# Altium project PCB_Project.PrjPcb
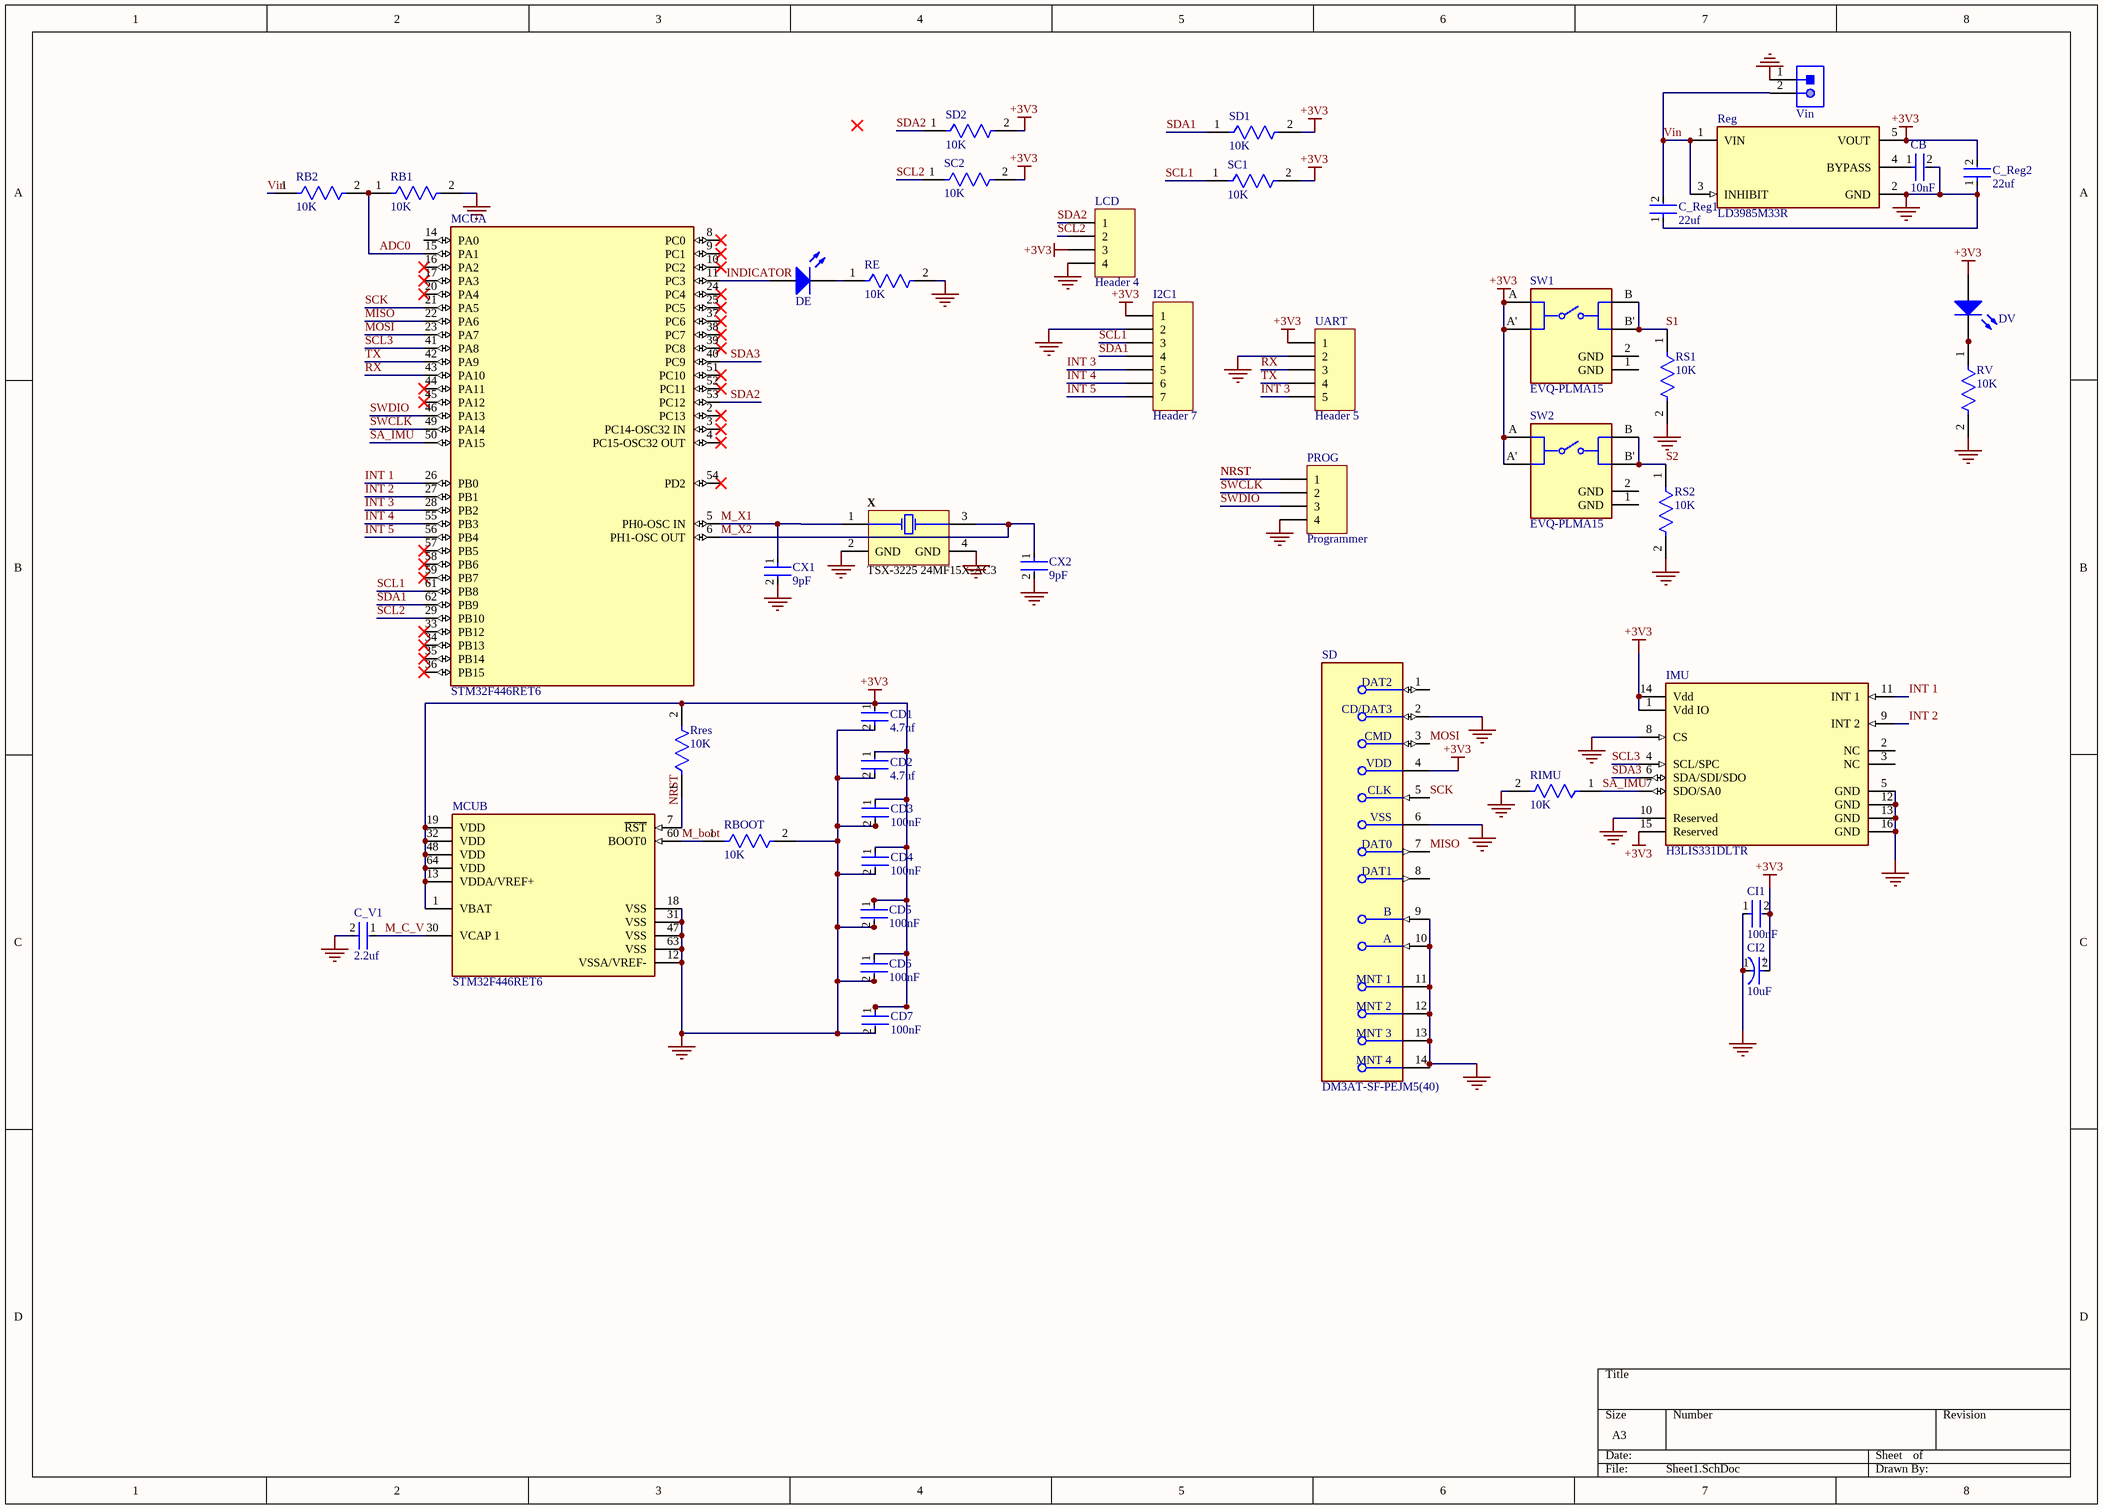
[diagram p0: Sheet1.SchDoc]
1 sheet, 42 parts. Net scope: global (net labels, ports and power ports of the same name join across sheets).
Board file: PCB1.PcbDoc

## Sheet Sheet1.SchDoc
size A3; SheetNumber: 1; SheetTotal: 1; SPICEModelCacheCNQVOYKR: <root> / <DocumentId>CNQVOYKR</DocumentId> / </root>

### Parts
C_Reg1  22uf  [FP-C2012-125-0_2-IPC_A]
C_Reg2  22uf  [FP-C2012-125-0_2-IPC_A]
C_V1  2.2uf  [FP-C1608-080-0_1-IPC_C]
CB  10nF  [FP-CC0603-DA-MFG]
CD1  4.7uf  [FP-C1608-080-0_1-IPC_C]
CD2  4.7uf  [FP-C1608-080-0_1-IPC_C]
CD3  100nF  [FP-CGA3E-0_3-0_1-IPC_A]
CD4  100nF  [FP-CGA3E-0_3-0_1-IPC_A]
CD5  100nF  [FP-CGA3E-0_3-0_1-IPC_A]
CD6  100nF  [FP-CGA3E-0_3-0_1-IPC_A]
CD7  100nF  [FP-CGA3E-0_3-0_1-IPC_A]
CI1  100nF  [FP-CGA3E-0_3-0_1-IPC_A]
CI2  10uF  [FP-SC-MFG]
CX1  9pF  [FP-CGA3E-0_3-0_1-IPC_B]
CX2  9pF  [FP-CGA3E-0_3-0_1-IPC_B]
DE  150080BS75000  [0805_A]  (value not drawn)
DV  150080BS75000  [0805_A]  (value not drawn)
I2C1  Header 7  [HDR1X7]
IMU  H3LIS331DLTR  [FP-TFLGA16-7983231-MFG]
LCD  Header 4  [HDR1X4]
MCU  STM32F446RET6  [FP-LQFP64-5W-MFG]  (parts A,B of 2)
PROG  Programmer  [HDR1X4]
RB1  10K  [FP-RC0603-0_55-IPC_C]
RB2  10K  [FP-RC0603-0_55-IPC_C]
RBOOT  10K  [FP-RC0603-0_55-IPC_C]
RE  10K  [FP-RC0603-0_55-IPC_C]
Reg  LD3985M33R  [FP-SOT23-5L-7049676-MFG]
RIMU  10K  [FP-RC0603-0_55-IPC_C]
Rres  10K  [FP-RC0603-0_55-IPC_C]
RS1  10K  [FP-RC0603-0_55-IPC_C]
RS2  10K  [FP-RC0603-0_55-IPC_C]
RV  10K  [FP-RC0603-0_55-IPC_C]
SC1  10K  [FP-RC0603-0_55-IPC_C]
SC2  10K  [FP-RC0603-0_55-IPC_C]
SD  DM3AT-SF-PEJM5(40)  [FP-DM3AT-SF-PEJM5_40-MFG]
SD1  10K  [FP-RC0603-0_55-IPC_C]
SD2  10K  [FP-RC0603-0_55-IPC_C]
SW1  EVQ-PLMA15  [FP-EVQ-PLMA15-MFG]
SW2  EVQ-PLMA15  [FP-EVQ-PLMA15-MFG]
UART  Header 5  [HDR1X5]
Vin  620302124022  [620302124022]  (value not drawn)
X  TSX-3225 24MF15X-AC3  [EPSON-TSX-3225_V]

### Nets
+3V3: C_Reg2.2 CD1.1 CD2.1 CD3.1 CD4.1 CD5.1 CD6.1 CD7.1 CI1.2 CI2.2(A) DV.2(A) I2C1.1 IMU.1(Vdd_IO) IMU.14(Vdd) IMU.15(Reserved) LCD.3 MCU.1(VBAT) MCU.13(VDDA/VREF+) MCU.19(VDD) MCU.32(VDD) MCU.48(VDD) MCU.64(VDD) Reg.5(VOUT) Rres.2 SC1.2 SC2.2 SD.4(VDD) SD1.2 SD2.2 SW1.A SW1.A' SW2.A SW2.A' UART.1
GND: C_Reg1.1 C_Reg2.1 C_V1.2 CB.2 CD1.2 CD2.2 CD3.2 CD4.2 CD5.2 CD6.2 CD7.2 CI1.1 CI2.1(C) CX1.2 CX2.2 I2C1.2 IMU.5(GND) IMU.8(CS) IMU.10(Reserved) IMU.12(GND) IMU.13(GND) IMU.16(GND) LCD.4 MCU.12(VSSA/VREF-) MCU.18(VSS) MCU.31(VSS) MCU.47(VSS) MCU.63(VSS) PROG.4 RB1.2 RBOOT.2 RE.2 Reg.2(GND) RIMU.2 RS1.2 RS2.2 RV.2 SD.2(CD/DAT3) SD.6(VSS) SD.9(B) SD.10(A) SD.11(MNT_1) SD.12(MNT_2) SD.13(MNT_3) SD.14(MNT_4) UART.2 Vin.1 X.2(GND) X.4(GND)
ADC0: MCU.15(PA1) RB1.1 RB2.2
INDICATOR: DE.2(A) MCU.11(PC3)
INT 1: IMU.11(INT_1) MCU.26(PB0)
INT 2: IMU.9(INT_2) MCU.27(PB1)
INT 3: I2C1.5 MCU.28(PB2) UART.5
INT 4: I2C1.6 MCU.55(PB3)
INT 5: I2C1.7 MCU.56(PB4)
M_boot: MCU.60(BOOT0) RBOOT.1
M_C_V: C_V1.1 MCU.30(VCAP_1)
M_X1: CX1.1 MCU.5(PH0-OSC_IN) X.1(X1)
M_X2: CX2.1 MCU.6(PH1-OSC_OUT) X.3(X2)
MISO: MCU.22(PA6) SD.7(DAT0)
MOSI: MCU.23(PA7) SD.3(CMD)
NRST: MCU.7(~{RST}) PROG.1 Rres.1
RX: MCU.43(PA10) UART.3
S1: RS1.1 SW1.B SW1.B'
S2: RS2.1 SW2.B SW2.B'
SA_IMU: IMU.7(SDO/SA0) MCU.50(PA15) RIMU.1
SCK: MCU.21(PA5) SD.5(CLK)
SCL1: I2C1.3 MCU.61(PB8) SC1.1
SCL2: LCD.2 MCU.29(PB10) SC2.1
SCL3: IMU.4(SCL/SPC) MCU.41(PA8)
SDA1: I2C1.4 MCU.62(PB9) SD1.1
SDA2: LCD.1 MCU.53(PC12) SD2.1
SDA3: IMU.6(SDA/SDI/SDO) MCU.40(PC9)
SWCLK: MCU.49(PA14) PROG.2
SWDIO: MCU.46(PA13) PROG.3
TX: MCU.42(PA9) UART.4
Vin: C_Reg1.2 RB2.1 Reg.1(VIN) Reg.3(INHIBIT) Vin.2
NetCB_1: CB.1 Reg.4(BYPASS)
NetDE_1: DE.1(K) RE.1
NetDV_1: DV.1(K) RV.1

Not connected (* = marked no-connect by the designer): IMU 2(NC) 3(NC); MCU 2(PC13)* 3(PC14-OSC32_IN)* 4(PC15-OSC32_OUT)* 8(PC0)* 9(PC1)* 10(PC2)* 14(PA0) 16(PA2)* 17(PA3)* 20(PA4)* 24(PC4)* 25(PC5)* 33(PB12)* 34(PB13)* 35(PB14)* 36(PB15)* 37(PC6)* 38(PC7)* 39(PC8)* 44(PA11)* 45(PA12)* 51(PC10)* 52(PC11)* 54(PD2)* 57(PB5)* 58(PB6)* 59(PB7)*; SD 1(DAT2) 8(DAT1); SW1 1(GND) 2(GND); SW2 1(GND) 2(GND)

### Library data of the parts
C_Reg1 C_Reg2 = CMP-08246-007072-1: Multilayer Ceramic Capacitors 22μF ±20% 16V X6S SMD 0805
C_V1 = CMP-2000-04981-2: Multilayer Ceramic Capacitors 4.7μF ±10% 16V X5R SMD 0603; Capacitance: 4.7uF
CB = CMP-2100-03600-2: CAP CER 10000PF 50V X7R 0603; Manufacturer Part Number: CC0603KRX7R9BB103; Manufacturer: YAGEO; Tolerance: 0.1; Temperature Coefficient: 15%
CD1 CD2 = CMP-2000-04981-2: Multilayer Ceramic Capacitors 4.7μF ±10% 16V X5R SMD 0603
CD3-CD7 CI1 = CMP-2000-07546-2: Cap Ceramic 100nF 50V X7R 10% Pad SMD 0603 +125°C Automotive T/R
CI2 = CMP-05427-000087-1: CAP ALUM 10UF 20% 35V SMD; Life (Hours): 2000Hour; Lead Length: 2.2mm; Ripple Current (AC): 30mA; Leakage Current: 3uA
CX1 CX2 = CMP-08246-000963-1: Cap Ceramic 9pF 50V C0G 0.5pF Pad SMD 0603 +125°C Automotive T/R
DE DV = CMP-1426-00008-1: SMD mono-color Chip LED, WL-SMCW, Blue; Manufacturer: Wuerth Elektronik
I2C1 = Header 7: Header, 7-Pin
IMU = CMP-12175-000002-1: ACCEL 100-400G I2C/SPI 16TFLGA; Manufacturer: STMicroelectronics; Min Supply Voltage: 2.16V; Accel Axis: X+Y and Z; Sensor Output: I2C,SPI; Accel Resolution: 16bits; Operating Supply Current: 10-300uA; Accel Range: 100/200/400g; Max Supply Voltage: 3.6V
LCD PROG = Header 4: Header, 4-Pin
MCU = CMP-12105-000007-1: IC MCU 32BIT 512KB FLASH 64LQFP; Manufacturer: ST; Number Of Spi Channels: 4; Ram Size: 128KBytes; Standoff Height: 0.05mm; Number Of Uart Channels: 6; Number Of Pwm Channels: 32; Max Junction Temp: +105°C; Number Of I/Os: 50; Number Of Usb Channels: 2; Frequency: 180MHz; Number Of A/D Converters: 3; Max Supply Voltage: 3.6V; Number Of Adc Channels: 16; Interface: I2C,SPI,UART,USART,CAN,USB,LIN,IrDA,I2S,Other; Memory Size: 512KBytes; Number Of Timers/Counters: 14; Min Supply Voltage: 1.7V; Core Architecture: ARM Cortex-M4; Data Bus Width: 32bits; Number Of Cores: 1
RB1 RB2 RBOOT RE RIMU Rres RS1 RS2 RV SC1 SC2 SD1 SD2 = CMP-2100-03664-2: RES 10K OHM 1% 1/10W 0603; Voltage Rating: 75V; Voltage Rating (DC): 50V; Resistance: 10kR; Power Rating: 100mW; Temperature Coefficient: 100ppm/°C
Reg = CMP-0244-00328-2: IC REG LINEAR 3.3V 150MA SOT23-5; Input Bias Current: 85uA; Output Type: Fixed; Max Input Voltage: 6V; Min Input Voltage: 2.5V; Output Voltage Accuracy: 2%; Quiescent Current: 150uA; Number of Regulators: 1; Min Current Limit: 300mA; Dropout Voltage: 60mV; Polarity: Positive
SD = CMP-11597-000006-1: CONN MICRO SD R/A PUSH-PUSH SMD; Contact Resistance: 100mR; Insulation Resistance: 1GR; Gender: Receptacle; Max Voltage Rating (AC): 125V; Pitch: 1.1mm; Mating Cycles: 10000; Max Current Rating: 500mA; Connector Type: Connector; Number of Contacts: 8
SW1 SW2 = CMP-05618-000006-1: SWITCH TACTILE SPST-NO 0.02A 15V; Manufacturer: Panasonic Electronic Components; Operating Force: 2.6N; Contact Resistance: 50mΩ; Contact Current Rating: 20mA; Electromechanical Life: 200000Cycles
UART = Header 5: Header, 5-Pin
Vin = CMP-1502-00660-1: Male Shrouded Header WR-WTB, SMT, Vertical, pitch 2 mm, 1 x 2 position; Manufacturer: Wurth Elektronik; Pitch: 2mm; Position: 1x2; Working Voltage: 100VAC; Contact Resistance: 20mOhm
X = CMP-2000-07333-1: MHz Range Crystal, 24 MHz, -40 to 85 degC, 4-Pin SMD, RoHS, Tape and Reel; Manufacturer: Epson; Brand: EpsonTiming; Frequency Stability: 10PPM; Frequency: 24MHz; ESR: 40Ohms; Load Capacitance: 9pF; Unit Weight: 0.000564oz; Drive Level: 200uW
